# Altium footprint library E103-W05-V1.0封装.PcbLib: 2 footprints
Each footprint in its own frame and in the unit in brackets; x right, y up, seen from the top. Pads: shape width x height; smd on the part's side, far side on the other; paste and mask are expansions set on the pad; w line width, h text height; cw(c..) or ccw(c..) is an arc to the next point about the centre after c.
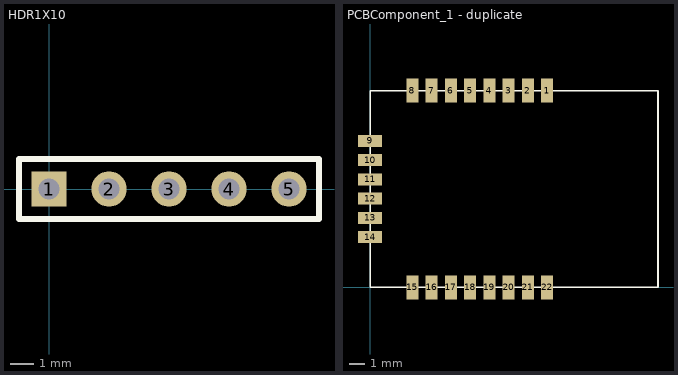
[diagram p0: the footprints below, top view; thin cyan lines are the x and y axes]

## HDR1X10 [mm] "Connector; Header; 10 Position"
pads (5):
  rect 1.5x1.5 hole 0.9: 1(0,0)
  round 1.5 hole 0.9: 2(2.54,0) 3(5.08,0) 4(7.62,0) 5(10.16,0)
Top Overlay:
  lines w0.254: -1.27,-1.27 11.43,-1.27 11.43,1.27 0.635,1.27 -1.27,1.27 -1.27,-1.27

## PCBComponent_1 - duplicate [mm]
pads (22):
  rect 0.8x1.6 smd: 1(11.682,13) 2(10.412,13) 3(9.142,13) 4(7.872,13) 5(6.602,13) 6(5.332,13) 7(4.062,13) 8(2.792,13) 15(2.792,0) 16(4.062,0) 17(5.332,0) 18(6.602,0) 19(7.872,0) 20(9.142,0) 21(10.412,0) 22(11.682,0)
  rect 1.6x0.8 smd: 9(0,9.675) 10(0,8.405) 11(0,7.135) 12(0,5.865) 13(0,4.595) 14(0,3.325)
Top Overlay:
  lines w0.1: 0,0 19,0 19,12.998 0,12.998 0,0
